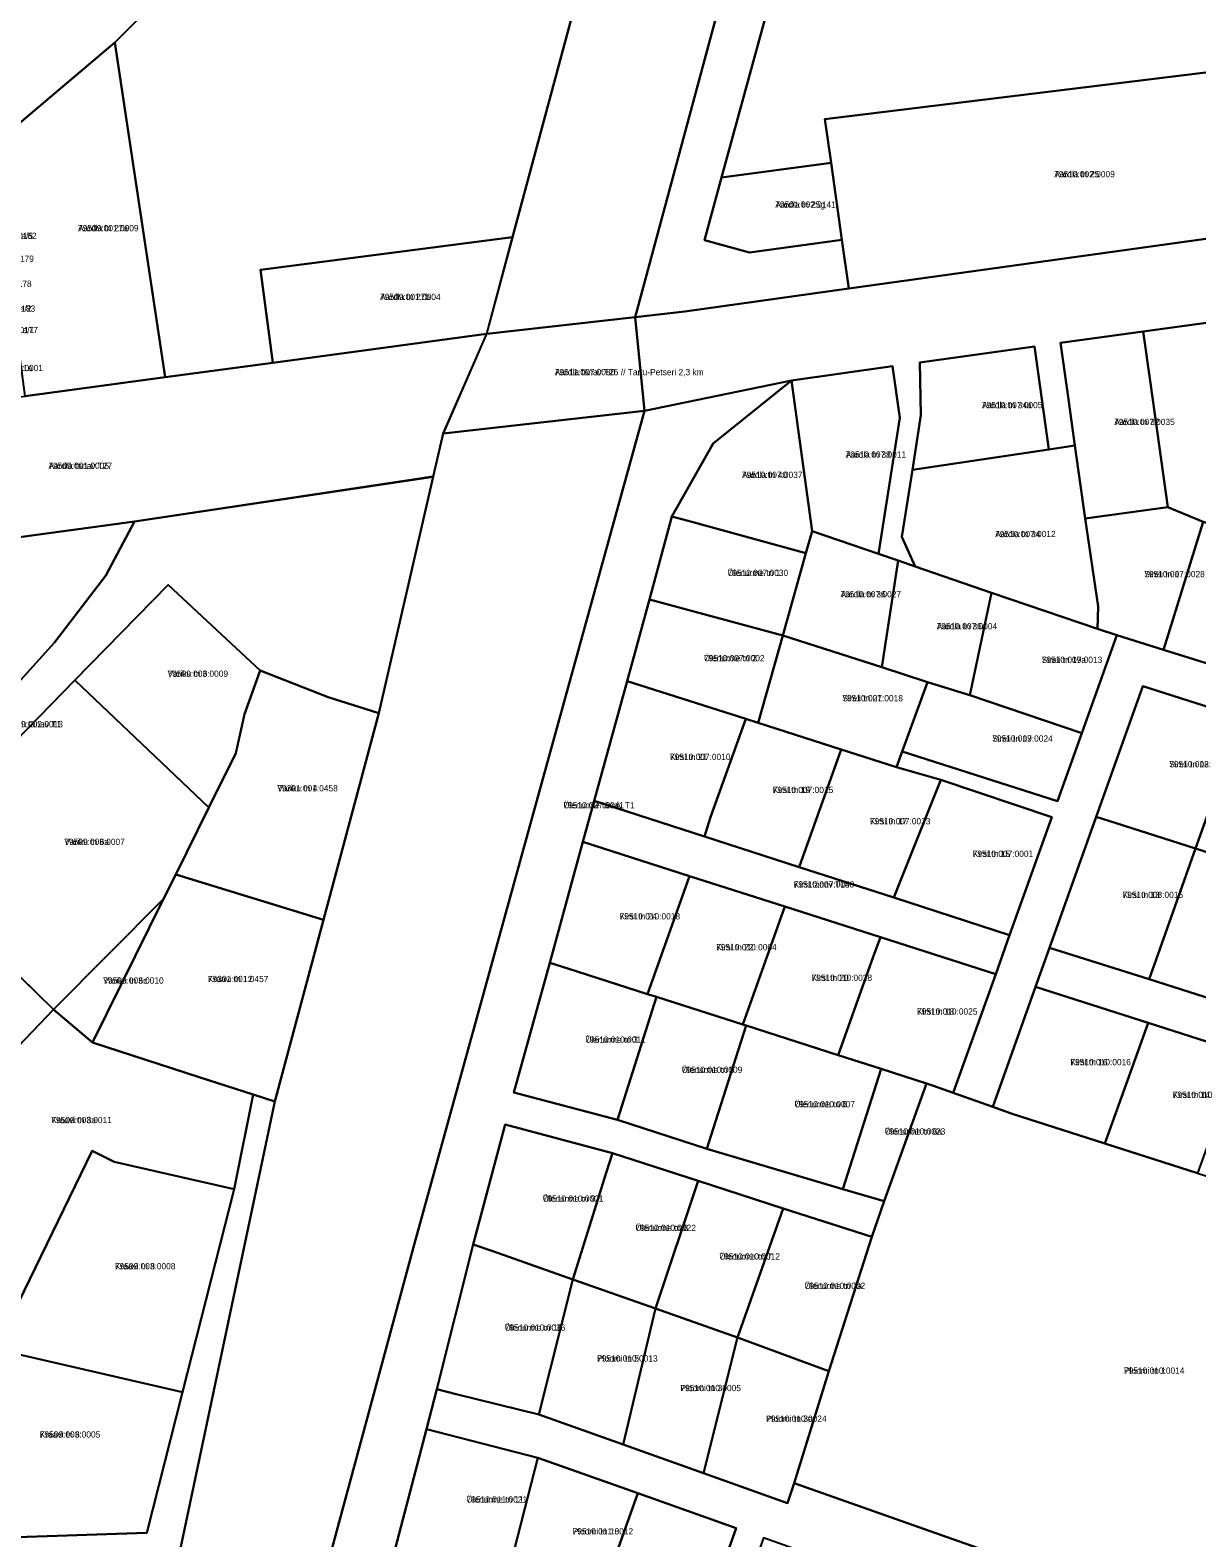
# Model space of a CAD drawing. Extents: x 643847 to 663718, y 6468443 to 6482775.
# Drawn here: x 658706.9 to 658986.5, y 6471208.6 to 6471569.9 of the extents above; entities that cross this region are included whole.
import ezdxf

# ---------------------------------------------------------------- set-up
doc = ezdxf.new("R2010")
doc.units = 0
for name, color, linetype in [('L_AADRESS', 7, 'Continuous'), ('PIIR', 7, 'Continuous'), ('TUNNUS', 7, 'Continuous')]:
    doc.layers.add(name, color=color, linetype=linetype)

msp = doc.modelspace()

# ---------------------------------------------------------------- linework, layer by layer
at = {"layer": 'PIIR'}
for points in [[(658872.56, 6471534.63), (658868.46, 6471519.62), (658879.26, 6471516.65), (658901.41, 6471519.63), (658903.07, 6471507.99), (658863.74, 6471502.5), (658851.85, 6471501.15), (658906.22, 6471702.62), (658908.57, 6471721.9), (658920.69, 6471723.17), (658924.76, 6471723.59), (658904.58, 6471651.21), (658890.88, 6471601.35)], [(658739.24, 6471486.75), (658727.17, 6471566.99), (658764.5, 6471604.37), (658796.7, 6471639.15), (658839.47, 6471693.83), (658866.19, 6471682.61), (658822.49, 6471520.27), (658762.09, 6471512.49), (658765.03, 6471490.22)], [(659001.65, 6471561.33), (658897.33, 6471548.58), (658898.81, 6471538.09), (658872.56, 6471534.63), (658890.88, 6471601.35), (658916.71, 6471604.34), (658917, 6471601.86), (658994.88, 6471610.86)], [(658739.24, 6471486.75), (658705.71, 6471482.19), (658704, 6471494.76), (658703.15, 6471500.91), (658702.34, 6471506.84), (658701.52, 6471512.76), (658700.71, 6471518.66), (658699.86, 6471524.81), (658698.19, 6471536.93), (658697.51, 6471541.86), (658727.16, 6471566.98)], [(658903.07, 6471507.99), (658901.41, 6471519.63), (658898.81, 6471538.09), (658897.33, 6471548.58), (659001.65, 6471561.33), (659006.97, 6471522.46)], [(658872.56, 6471534.63), (658898.81, 6471538.09), (658901.41, 6471519.63), (658879.26, 6471516.65), (658868.46, 6471519.62)], [(658762.09, 6471512.49), (658822.49, 6471520.27), (658816.26, 6471497.13), (658765.03, 6471490.22)], [(658816.31, 6471497.12), (658851.85, 6471501.15), (658854.07, 6471478.7), (658805.86, 6471473.27)], [(658993.43, 6471500.43), (658995.16, 6471488.05), (658999.31, 6471458.32), (659000.7, 6471448.41), (658988, 6471452.11), (658979.52, 6471455.59), (658975.35, 6471485.32), (658973.62, 6471497.7)], [(658816.26, 6471497.13), (658805.86, 6471473.23), (658803.49, 6471462.92), (658731.9, 6471452.14), (658649.17, 6471440.87), (658580.57, 6471432.42), (658591.46, 6471443.7), (658611.17, 6471463.76), (658624.1, 6471465.51), (658630.46, 6471471.99), (658636.33, 6471472.79), (658648.5, 6471474.43), (658659.81, 6471475.95), (658667.75, 6471477.03), (658675.61, 6471478.09), (658679.59, 6471478.63), (658687.17, 6471479.62), (658705.71, 6471482.19), (658739.24, 6471486.75), (658765.03, 6471490.22)], [(658953.82, 6471494.97), (658973.62, 6471497.7), (658975.35, 6471485.32), (658979.52, 6471455.59), (658959.74, 6471452.85), (658957.21, 6471470.39), (658955.53, 6471482.58)], [(658947.53, 6471494.11), (658950.97, 6471469.45), (658918.3, 6471464.54), (658920.34, 6471477.68), (658920.05, 6471490.27)], [(658913.56, 6471489.37), (658915.3, 6471476.98), (658910.18, 6471444.42), (658894.29, 6471449.85), (658891, 6471473.62), (658889.3, 6471485.99)], [(658870.59, 6471470.84), (658889.3, 6471485.99), (658891, 6471473.62), (658894.29, 6471449.85), (658892.8, 6471444.61), (658865.48, 6471452.06), (658860.66, 6471453.37)], [(658950.97, 6471469.45), (658957.21, 6471470.39), (658959.74, 6471452.85), (658962.82, 6471431.76), (658962.69, 6471426.44), (658937.26, 6471435.08), (658918.98, 6471441.4), (658915.81, 6471448.53), (658918.3, 6471464.54)], [(658667.9, 6471374.64), (658681.84, 6471388.98), (658712.74, 6471423.15), (658725.04, 6471439.2), (658731.9, 6471452.14), (658803.46, 6471462.91), (658790.44, 6471406.27), (658778.27, 6471410.06), (658762.02, 6471416.49), (658739.98, 6471437.01), (658717.62, 6471414.12), (658680.43, 6471376.08), (658675.68, 6471371.23), (658626.31, 6471320.49), (658606.07, 6471299.73), (658597.05, 6471308.95), (658605.51, 6471310.48), (658620.85, 6471326.25), (658641.07, 6471347.04), (658655.01, 6471361.37)], [(658967.25, 6471424.89), (658962.69, 6471426.44), (658962.82, 6471431.76), (658959.74, 6471452.85), (658979.52, 6471455.59), (658988, 6471452.11), (658980, 6471426.28), (658978.48, 6471421.39)], [(658731.9, 6471452.14), (658725.04, 6471439.2), (658712.74, 6471423.15), (658681.84, 6471388.98), (658656.74, 6471413.37), (658640.69, 6471411.78), (658649.17, 6471440.87)], [(658865.48, 6471452.06), (658892.8, 6471444.61), (658887.25, 6471424.85), (658855.27, 6471433.44), (658860.66, 6471453.37)], [(658999.46, 6471414.85), (658978.48, 6471421.39), (658980, 6471426.28), (658988, 6471452.11), (659000.7, 6471448.41), (659009.16, 6471445.36), (659000.97, 6471419.6)], [(658910.96, 6471417.29), (658887.25, 6471424.85), (658892.8, 6471444.61), (658894.29, 6471449.85), (658910.18, 6471444.42), (658914.91, 6471442.81)], [(658918.98, 6471441.4), (658937.26, 6471435.08), (658932.08, 6471410.56), (658921.96, 6471413.68), (658910.96, 6471417.29), (658914.91, 6471442.81)], [(658717.62, 6471414.12), (658739.98, 6471437.01), (658762.02, 6471416.49), (658758.3, 6471406), (658756.18, 6471396.68), (658749.73, 6471383.65)], [(658855.27, 6471433.44), (658887.25, 6471424.85), (658881.34, 6471403.9), (658878.36, 6471404.86), (658854.74, 6471412.41), (658849.98, 6471413.94)], [(658958.89, 6471401.48), (658932.08, 6471410.56), (658937.26, 6471435.08), (658962.69, 6471426.44), (658967.25, 6471424.89)], [(658910.96, 6471417.29), (658921.96, 6471413.68), (658915.83, 6471397.03), (658914.46, 6471393.31), (658901.22, 6471397.54), (658881.34, 6471403.9), (658887.25, 6471424.85)], [(658778.27, 6471410.06), (658790.44, 6471406.27), (658777.16, 6471356.71), (658741.8, 6471367.61), (658749.73, 6471383.65), (658756.18, 6471396.68), (658758.3, 6471406), (658762.02, 6471416.49)], [(658717.62, 6471414.12), (658749.73, 6471383.65), (658741.8, 6471367.61), (658738.88, 6471361.71), (658712.51, 6471335.21), (658682.39, 6471364.66), (658687.14, 6471369.52), (658680.43, 6471376.08)], [(658842.07, 6471385.22), (658849.98, 6471413.94), (658854.74, 6471412.41), (658878.36, 6471404.86), (658869.96, 6471381.31), (658868.47, 6471376.69)], [(658953.05, 6471385.14), (658915.83, 6471397.03), (658921.96, 6471413.68), (658932.08, 6471410.56), (658958.89, 6471401.48)], [(658973.51, 6471412.7), (658997.34, 6471405.1), (658995.66, 6471400.39), (658986.17, 6471373.8), (658967.1, 6471379.88), (658962.33, 6471381.4)], [(658868.47, 6471376.69), (658869.96, 6471381.31), (658878.36, 6471404.86), (658881.34, 6471403.9), (658901.22, 6471397.54), (658891.16, 6471369.36)], [(659016.39, 6471398.99), (659014.71, 6471394.28), (659005.22, 6471367.71), (658986.17, 6471373.8), (658995.66, 6471400.39), (658997.34, 6471405.1)], [(658891.16, 6471369.36), (658901.22, 6471397.54), (658914.46, 6471393.31), (658925.08, 6471390.27), (658915.68, 6471366.68), (658913.82, 6471362.03)], [(658913.82, 6471362.03), (658915.68, 6471366.68), (658925.08, 6471390.27), (658951.69, 6471381.31), (658941.6, 6471353.06)], [(658941.6, 6471353.06), (658938.26, 6471343.7), (658910.62, 6471352.56), (658887.76, 6471359.88), (658864.9, 6471367.19), (658839.36, 6471375.37), (658842.07, 6471385.22), (658868.47, 6471376.69), (658891.16, 6471369.36), (658913.82, 6471362.03)], [(658975, 6471342.51), (658951.15, 6471350.04), (658962.33, 6471381.4), (658967.1, 6471379.88), (658986.17, 6471373.8), (658976.68, 6471347.22)], [(658864.9, 6471367.19), (658863.22, 6471362.49), (658854.81, 6471338.94), (658835.76, 6471345.03), (658831.39, 6471346.43), (658839.36, 6471375.37)], [(658975, 6471342.51), (658976.68, 6471347.22), (658986.17, 6471373.8), (659005.22, 6471367.71), (658995.73, 6471341.14), (658994.05, 6471336.43)], [(658642.77, 6471304.43), (658626.31, 6471320.49), (658675.68, 6471371.23), (658712.51, 6471335.21), (658663.59, 6471284.1)], [(658738.88, 6471361.71), (658741.8, 6471367.61), (658777.16, 6471356.71), (658765.5, 6471313.17), (658760.36, 6471314.82), (658747.43, 6471319), (658721.8, 6471327.33)], [(658887.76, 6471359.88), (658886.08, 6471355.17), (658877.67, 6471331.62), (658857, 6471338.23), (658854.81, 6471338.94), (658863.22, 6471362.49), (658864.9, 6471367.19)], [(658738.88, 6471361.71), (658721.8, 6471327.33), (658712.51, 6471335.21)], [(658887.76, 6471359.88), (658910.62, 6471352.56), (658908.94, 6471347.85), (658900.54, 6471324.3), (658878.43, 6471331.37), (658877.67, 6471331.62), (658886.08, 6471355.17)], [(658938.26, 6471343.7), (658928.1, 6471315.27), (658923.39, 6471316.97), (658921.71, 6471317.51), (658910.82, 6471321.01), (658900.54, 6471324.3), (658908.94, 6471347.85), (658910.62, 6471352.56)], [(659094.02, 6471304.55), (659090.43, 6471294.81), (659063.64, 6471303.63), (659041.42, 6471310.73), (659019.2, 6471317.83), (658996.98, 6471324.94), (658974.77, 6471332.05), (658947.78, 6471340.68), (658951.15, 6471350.04), (658975, 6471342.51), (658994.05, 6471336.43), (659013.1, 6471330.34), (659032.15, 6471324.25), (659051.2, 6471318.16), (659070.26, 6471312.06)], [(658831.39, 6471346.43), (658835.76, 6471345.03), (658854.81, 6471338.94), (658857, 6471338.23), (658847.64, 6471308.78), (658822.83, 6471315.35)], [(658974.77, 6471332.05), (658973.08, 6471327.33), (658964.4, 6471303.08), (658942.23, 6471310.21), (658937.55, 6471311.92), (658947.78, 6471340.68)], [(658847.64, 6471308.78), (658857, 6471338.23), (658877.67, 6471331.62), (658878.43, 6471331.37), (658870.56, 6471306.6), (658869.04, 6471301.83)], [(658712.51, 6471335.21), (658721.8, 6471327.33), (658747.43, 6471319), (658760.36, 6471314.82), (658755.78, 6471292.14), (658727.03, 6471298.7), (658721.72, 6471301.39), (658698.63, 6471253.86), (658686.74, 6471256.66), (658663.59, 6471284.1)], [(658973.08, 6471327.33), (658974.77, 6471332.05), (658996.98, 6471324.94), (658995.3, 6471320.22), (658986.62, 6471296.03), (658964.4, 6471303.08)], [(658869.04, 6471301.83), (658870.56, 6471306.6), (658878.43, 6471331.37), (658900.54, 6471324.3), (658910.82, 6471321.01), (658901.65, 6471292.19)], [(658921.71, 6471317.51), (658911.5, 6471289.28), (658901.65, 6471292.19), (658910.82, 6471321.01)], [(658911.5, 6471289.28), (658921.71, 6471317.51), (658923.39, 6471316.97), (658928.1, 6471315.27), (658937.55, 6471311.92), (658942.23, 6471310.21), (658964.4, 6471303.08), (658986.62, 6471296.03), (659008.9, 6471288.89), (659031.13, 6471281.77), (659049.85, 6471275.8), (659042.37, 6471254.9), (659034.97, 6471234.19), (659033.06, 6471234.76), (659026.61, 6471216.62), (659019.78, 6471197.55), (659012.93, 6471178.37), (658889.96, 6471221.72), (658898.3, 6471248.52), (658908.55, 6471280.75)], [(658705.68, 6471045.12), (658708.5, 6471071.36), (658713.16, 6471114.65), (658711.56, 6471118.9), (658707.89, 6471121.35), (658706.11, 6471129.75), (658689.82, 6471203.36), (658698.88, 6471208.62), (658734.86, 6471209.81), (658743.38, 6471243.53), (658755.78, 6471292.14), (658760.36, 6471314.82), (658765.5, 6471313.17), (658760.7, 6471290.4), (658727.38, 6471132.36), (658718.47, 6471080.15), (658713.7, 6471023.88), (658711.74, 6470952.85), (658701.04, 6470949.42), (658701.84, 6470983.89), (658702.59, 6471016.34)], [(658820.71, 6471307.64), (658846.43, 6471300.83), (658844.94, 6471296.06), (658836.94, 6471270.55), (658817.79, 6471277.28), (658813.07, 6471278.94)], [(658721.72, 6471301.39), (658727.03, 6471298.7), (658755.78, 6471292.14), (658743.38, 6471243.53), (658698.63, 6471253.86)], [(658866.94, 6471294.14), (658856.74, 6471263.59), (658836.94, 6471270.55), (658844.94, 6471296.06), (658846.43, 6471300.83)], [(658887.36, 6471287.52), (658876.42, 6471256.59), (658856.74, 6471263.59), (658866.94, 6471294.14)], [(658876.42, 6471256.59), (658887.36, 6471287.52), (658908.55, 6471280.75), (658898.3, 6471248.52)], [(658813.07, 6471278.94), (658817.79, 6471277.28), (658836.94, 6471270.55), (658828.77, 6471238.21), (658808.99, 6471243.08), (658804.34, 6471244.23)], [(658828.77, 6471238.21), (658836.94, 6471270.55), (658856.74, 6471263.59), (658848.99, 6471230.99)], [(658848.99, 6471230.99), (658856.74, 6471263.59), (658876.42, 6471256.59), (658868.21, 6471224.1)], [(658697.92, 6471213.01), (658670.35, 6471239.87), (658686.74, 6471256.66), (658698.64, 6471253.86), (658743.38, 6471243.53), (658734.86, 6471209.81), (658698.88, 6471208.62)], [(658889.96, 6471221.72), (658888.39, 6471216.96), (658868.21, 6471224.1), (658876.42, 6471256.59), (658898.3, 6471248.52)], [(658828.51, 6471227.8), (658821.25, 6471199.46), (658794.43, 6471206.34), (658801.91, 6471234.62)], [(658852.5, 6471219.31), (658842.8, 6471191.96), (658821.25, 6471199.46), (658828.51, 6471227.8)], [(658876.05, 6471210.95), (658866.36, 6471183.61), (658842.8, 6471191.96), (658852.5, 6471219.31)]]:
    msp.add_lwpolyline(points, close=True, dxfattribs=at)
for points in [[(658906.22, 6471702.62), (658851.85, 6471501.15), (658816.31, 6471497.12), (658822.49, 6471520.27), (658866.19, 6471682.61)], [(658764.5, 6471604.37), (658727.16, 6471566.98), (658697.51, 6471541.86), (658688.1, 6471533.89), (658683.33, 6471532.89), (658675.1, 6471524.51), (658675.8, 6471518.22), (658670.81, 6471513.13), (658665.27, 6471507.48), (658661.16, 6471503.29), (658657.1, 6471499.15), (658653.16, 6471495.13), (658648.81, 6471490.7), (658646.57, 6471488.41), (658630.46, 6471471.99), (658624.1, 6471465.51), (658611.17, 6471463.76), (658565.45, 6471457.56), (658586.66, 6471477.59), (658677.6, 6471570.91)], [(658993.43, 6471500.43), (658973.62, 6471497.7), (658953.82, 6471494.97), (658955.53, 6471482.58), (658957.21, 6471470.39), (658950.97, 6471469.45), (658947.53, 6471494.11), (658920.05, 6471490.27), (658920.34, 6471477.68), (658918.3, 6471464.54), (658915.81, 6471448.53), (658918.98, 6471441.4), (658914.91, 6471442.81), (658910.18, 6471444.42), (658915.3, 6471476.98), (658913.56, 6471489.37), (658889.3, 6471485.99), (658854.07, 6471478.7), (658851.85, 6471501.15), (658863.74, 6471502.5), (658903.07, 6471507.99), (659006.97, 6471522.46)], [(658770.29, 6471173.16), (658798.96, 6471279.15), (658854.07, 6471478.7), (658889.3, 6471485.99), (658870.59, 6471470.84), (658860.66, 6471453.37), (658855.27, 6471433.44), (658849.98, 6471413.94), (658842.07, 6471385.22), (658839.36, 6471375.37), (658831.39, 6471346.43), (658822.83, 6471315.35), (658847.64, 6471308.78), (658869.04, 6471301.83), (658901.65, 6471292.19), (658911.5, 6471289.28), (658908.55, 6471280.75), (658887.36, 6471287.52), (658866.94, 6471294.14), (658846.43, 6471300.83), (658820.71, 6471307.64), (658813.07, 6471278.94), (658804.34, 6471244.23), (658801.91, 6471234.62), (658794.43, 6471206.34)], [(658715.37, 6470870.27), (658711.74, 6470952.85), (658713.7, 6471023.88), (658718.47, 6471080.15), (658727.38, 6471132.36), (658765.5, 6471313.17), (658777.16, 6471356.71), (658790.44, 6471406.27), (658803.46, 6471462.91), (658805.86, 6471473.27), (658854.07, 6471478.7), (658798.96, 6471279.15), (658770.29, 6471173.16), (658757.86, 6471104.24), (658749.35, 6471038.5), (658746.57, 6470967.46), (658748.37, 6470894.81)], [(658997.34, 6471405.1), (658973.51, 6471412.7), (658962.33, 6471381.4), (658951.15, 6471350.04), (658947.78, 6471340.68), (658937.55, 6471311.92), (658928.1, 6471315.27), (658938.26, 6471343.7), (658941.6, 6471353.06), (658951.69, 6471381.31), (658925.08, 6471390.27), (658914.46, 6471393.31), (658915.83, 6471397.03), (658953.05, 6471385.14), (658958.89, 6471401.48), (658967.25, 6471424.89), (658978.48, 6471421.39), (658999.46, 6471414.85)], [(658995.53, 6471168.6), (658975.7, 6471175.63), (658953.32, 6471183.56), (658929.76, 6471191.92), (658906.21, 6471200.26), (658882.65, 6471208.61), (658872.96, 6471181.27), (658869.64, 6471182.45), (658866.36, 6471183.61), (658876.05, 6471210.95), (658852.5, 6471219.31), (658828.51, 6471227.8), (658801.91, 6471234.62), (658804.34, 6471244.23), (658808.99, 6471243.08), (658828.77, 6471238.21), (658848.99, 6471230.99), (658868.21, 6471224.1), (658888.39, 6471216.96), (658889.96, 6471221.72), (659012.93, 6471178.37)]]:
    msp.add_lwpolyline(points, dxfattribs=at)

# ---------------------------------------------------------------- texts
at = {"layer": 'L_AADRESS'}
for s, p in [('Aardla tn 25', (658952.3, 6471534.66)), ('Aardla tn 25g', (658885.45, 6471527.37)), ('Aardla tn 27a', (658718.38, 6471521.72)), ('Aardla tn 31a/5', (658693.96, 6471519.87)), ('Aardla tn 27b', (658790.75, 6471505.24)), ('Aardla tn 31a/2', (658693.6, 6471502.44)), ('Aardla tn 31a/1', (658694.27, 6471497.3)), ('Aardla tn 31a', (658695.47, 6471488.2)), ('Aardla tänav T25 // Tartu-Petseri 2,3 km', (658832.6, 6471487.21)), ('Aardla tn 34a', (658934.95, 6471479.32)), ('Aardla tn 32', (658966.67, 6471475.28)), ('Aardla tänav T27', (658711.29, 6471464.78)), ('Aardla tn 38', (658902.3, 6471467.46)), ('Aardla tn 40', (658877.47, 6471462.6)), ('Aardla tn 34', (658938.12, 6471448.42)), ('Ülenurme tn 1', (658874.03, 6471439.11)), ('Sireli tn 17', (658973.87, 6471438.82)), ('Aardla tn 36', (658901.08, 6471433.98)), ('Aardla tn 36a', (658924.11, 6471426.32)), ('Ülenurme tn 2', (658868.38, 6471418.67)), ('Sireli tn 19a', (658949.3, 6471418.28)), ('Variku tn 6', (658739.82, 6471414.95)), ('Sireli tn 21', (658901.53, 6471409.08)), ('Variku tänav T1', (658700.25, 6471402.85)), ('Sireli tn 19', (658937.43, 6471399.41)), ('Kirsi tn 21', (658860.21, 6471395.01)), ('Sireli tn 12', (658979.84, 6471393.25)), ('Variku tn 4', (658766.12, 6471387.49)), ('Kirsi tn 19', (658884.84, 6471387.09)), ('Ülenurme tänav T1', (658834.68, 6471383.43)), ('Kirsi tn 17', (658908.12, 6471379.6)), ('Variku tn 6a', (658715.08, 6471374.66)), ('Kirsi tn 15', (658932.75, 6471371.8)), ('Kirsi tänav T15', (658889.87, 6471364.46)), ('Kirsi tn 13', (658968.66, 6471361.95)), ('Kirsi tn 24', (658848.14, 6471356.81)), ('Kirsi tn 22', (658871.29, 6471349.41)), ('Variku tn 6c', (658724.4, 6471341.42)), ('Kraavi tn 12', (658749.48, 6471341.79)), ('Kirsi tn 20', (658894.14, 6471342.09)), ('Kirsi tn 18', (658919.4, 6471334)), ('Ülenurme tn 3', (658839.91, 6471327.26)), ('Ülenurme tn 5', (658863.04, 6471320.04)), ('Kirsi tn 16', (658956.16, 6471321.87)), ('Kirsi tn 14', (658980.69, 6471314.03)), ('Ülenurme tn 6', (658890.04, 6471311.78)), ('Kraavi tn 8a', (658711.98, 6471307.99)), ('Ülenurme tn 6a', (658911.68, 6471305.26)), ('Ülenurme tn 9', (658829.75, 6471289.16)), ('Ülenurme tn 8', (658851.94, 6471282.16)), ('Kraavi tn 8', (658727.21, 6471272.96)), ('Ülenurme tn 7', (658872.05, 6471275.31)), ('Ülenurme tn 7a', (658892.48, 6471268.27)), ('Ülenurme tn 10', (658820.64, 6471258.25)), ('Ploomi tn 5', (658842.76, 6471250.86)), ('Ploomi tn 1', (658969, 6471247.94)), ('Ploomi tn 3', (658862.71, 6471243.77)), ('Ploomi tn 3a', (658883.25, 6471236.42)), ('Kraavi tn 6', (658709.2, 6471232.64)), ('Ülenurme tn 11', (658811.47, 6471217.07)), ('Ploomi tn 18', (658836.88, 6471209.43))]:
    msp.add_text(s, height=1.5, dxfattribs=at).set_placement(p)
at = {"layer": 'TUNNUS'}
for s, p in [('79510:002:0009', (658952.3, 6471534.66)), ('79501:002:0141', (658885.45, 6471527.37)), ('79301:001:0182', (658693.96, 6471519.87)), ('79509:001:0009', (658718.38, 6471521.72)), ('79301:001:0179', (658693.3, 6471514.4)), ('79301:001:0178', (658692.75, 6471508.4)), ('79509:001:0004', (658790.75, 6471505.24)), ('79301:001:0183', (658693.6, 6471502.44)), ('79301:001:0177', (658694.27, 6471497.3)), ('79509:001:0001', (658695.47, 6471488.2)), ('79511:007:0080', (658832.6, 6471487.21)), ('79510:007:0005', (658934.95, 6471479.32)), ('79510:007:0035', (658966.67, 6471475.28)), ('79509:001:0005', (658711.29, 6471464.78)), ('79510:007:0011', (658902.3, 6471467.46)), ('79510:007:0037', (658877.47, 6471462.6)), ('79510:007:0012', (658938.12, 6471448.42)), ('79510:007:0030', (658874.03, 6471439.11)), ('79510:007:0028', (658973.87, 6471438.82)), ('79510:007:0027', (658901.08, 6471433.98)), ('79510:007:0004', (658924.11, 6471426.32)), ('79510:007:0002', (658868.38, 6471418.67)), ('79510:007:0013', (658949.3, 6471418.28)), ('79509:003:0009', (658739.82, 6471414.95)), ('79510:007:0018', (658901.53, 6471409.08)), ('79509:002:0013', (658700.25, 6471402.85)), ('79510:007:0024', (658937.43, 6471399.41)), ('79510:007:0010', (658860.21, 6471395.01)), ('79510:008:0011', (658979.84, 6471393.25)), ('79301:001:0458', (658766.12, 6471387.49)), ('79510:007:0015', (658884.84, 6471387.09)), ('79510:007:0041', (658834.68, 6471383.43)), ('79510:007:0023', (658908.12, 6471379.6)), ('79509:003:0007', (658715.08, 6471374.66)), ('79510:007:0001', (658932.75, 6471371.8)), ('79510:007:0040', (658889.87, 6471364.46)), ('79510:008:0015', (658968.66, 6471361.95)), ('79510:010:0018', (658848.14, 6471356.81)), ('79510:010:0004', (658871.29, 6471349.41)), ('79509:003:0010', (658724.4, 6471341.42)), ('79301:001:0457', (658749.48, 6471341.79)), ('79510:010:0028', (658894.14, 6471342.09)), ('79510:010:0025', (658919.4, 6471334)), ('79510:010:0011', (658839.91, 6471327.26)), ('79510:010:0009', (658863.04, 6471320.04)), ('79510:010:0016', (658956.16, 6471321.87)), ('79510:010:0010', (658980.69, 6471314.03)), ('79510:010:0007', (658890.04, 6471311.78)), ('79509:003:0011', (658711.98, 6471307.99)), ('79510:010:0023', (658911.68, 6471305.26)), ('79510:010:0001', (658829.75, 6471289.16)), ('79510:010:0022', (658851.94, 6471282.16)), ('79509:003:0008', (658727.21, 6471272.96)), ('79510:010:0012', (658872.05, 6471275.31)), ('79510:010:0002', (658892.48, 6471268.27)), ('79510:010:0026', (658820.64, 6471258.25)), ('79510:010:0013', (658842.76, 6471250.86)), ('79510:010:0014', (658969, 6471247.94)), ('79510:010:0005', (658862.71, 6471243.77)), ('79510:010:0024', (658883.25, 6471236.42)), ('79509:003:0005', (658709.2, 6471232.64)), ('79510:011:0021', (658811.47, 6471217.07)), ('79510:011:0012', (658836.88, 6471209.43))]:
    msp.add_text(s, height=1.5, dxfattribs=at).set_placement(p)

doc.saveas('drawing.dxf')
